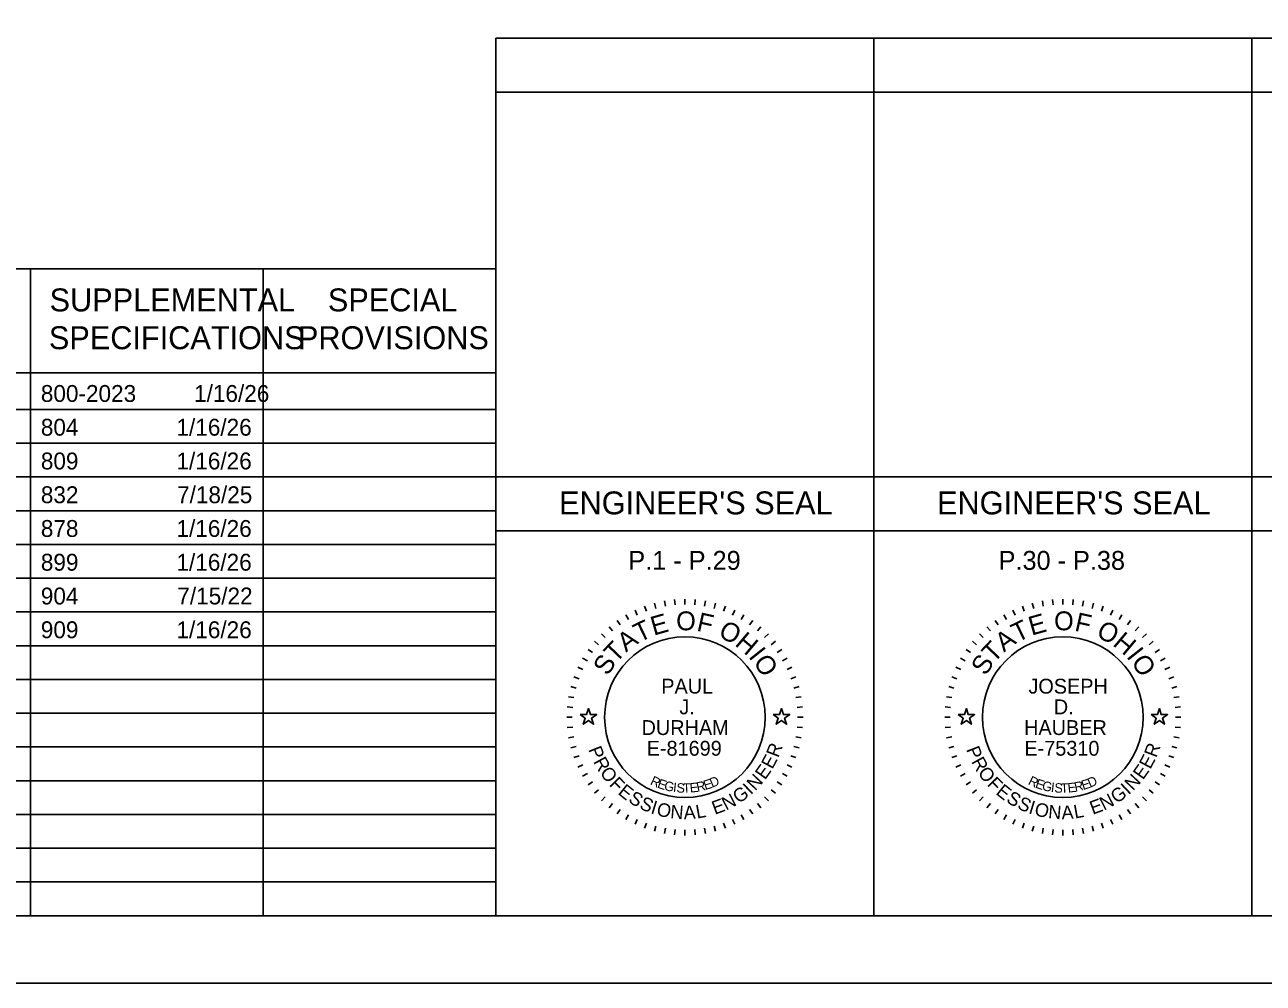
# Model space of a CAD drawing. Extents: x 0 to 34, y 0 to 22.
# Drawn here: x 20.11 to 29.28, y 0 to 7.1 of the extents above; entities that cross this region are included whole.
import ezdxf

# ---------------------------------------------------------------- set-up
doc = ezdxf.new("R2010")
doc.units = 0
for name, color, linetype in [('SH_Border', 7, 'Continuous'), ('SH_Cut_Line', 7, 'Continuous'), ('SH_Data', 7, 'Continuous'), ('SH_Seal', 7, 'Continuous'), ('SH_Text', 7, 'Continuous')]:
    doc.layers.add(name, color=color, linetype=linetype)

msp = doc.modelspace()

# ---------------------------------------------------------------- linework, layer by layer
at = {"layer": 'SH_Border'}
msp.add_lwpolyline([(1.5, 21.5), (33.5, 21.5), (33.5, 0.5), (1.5, 0.5)], close=True, dxfattribs=at)
at = {"layer": 'SH_Cut_Line'}
msp.add_lwpolyline([(0, 0), (34, 0), (34, 22), (0, 22)], close=True, dxfattribs=at)
at = {"layer": 'SH_Data'}
for p, q in [((23.6, 6.6), (26.4, 6.6)), ((26.4, 6.6), (29.2, 6.6)), ((29.2, 6.6), (32, 6.6)), ((10.15, 5.2917), (23.6, 5.2917)), ((20.15, 0.5), (20.15, 5.2917)), ((21.875, 0.5), (21.875, 5.2917)), ((23.6, 0.5), (23.6, 5.2917)), ((10.15, 4.5209), (23.6, 4.5209)), ((10.15, 4.25), (23.6, 4.25)), ((10.15, 4), (23.6, 4)), ((10.15, 3.75), (23.6, 3.75)), ((23.6, 3.75), (26.4, 3.75)), ((26.4, 0.5), (26.4, 3.75)), ((26.4, 3.75), (29.2, 3.75)), ((29.2, 0.5), (29.2, 3.75)), ((10.15, 3.5), (23.6, 3.5)), ((23.6, 3.35), (26.4, 3.35)), ((23.6, 3.35), (26.4, 3.35)), ((26.4, 3.35), (29.2, 3.35)), ((26.4, 3.35), (29.2, 3.35)), ((29.2, 3.35), (32, 3.35)), ((10.15, 3.25), (23.6, 3.25)), ((10.15, 3), (23.6, 3)), ((10.15, 2.75), (23.6, 2.75)), ((10.15, 2.5), (23.6, 2.5)), ((10.15, 2.25), (23.6, 2.25)), ((10.15, 2), (23.6, 2)), ((10.15, 1.75), (23.6, 1.75)), ((10.15, 1.5), (23.6, 1.5)), ((10.15, 1.25), (23.6, 1.25)), ((10.15, 1), (23.6, 1)), ((10.15, 0.75), (23.6, 0.75))]:
    msp.add_line(p, q, dxfattribs=at)
for points in [[(26.4, 7), (23.6, 7), (23.6, 3.75), (26.4, 3.75)], [(29.2, 7), (26.4, 7), (26.4, 3.75), (29.2, 3.75)], [(32, 7), (29.2, 7), (29.2, 3.75), (32, 3.75)], [(26.4, 3.75), (23.6, 3.75), (23.6, 0.5), (26.4, 0.5)], [(29.2, 3.75), (26.4, 3.75), (26.4, 0.5), (29.2, 0.5)], [(32, 3.75), (29.2, 3.75), (29.2, 0.5), (32, 0.5)]]:
    msp.add_lwpolyline(points, close=True, dxfattribs=at)
at = {"layer": 'SH_Seal'}
for p, q in [((25, 2.8452), (25, 2.8052)), ((27.8, 2.8452), (27.8, 2.8052)), ((24.6302, 2.7633), (24.6471, 2.727)), ((24.7007, 2.7925), (24.7144, 2.7549)), ((24.7735, 2.8154), (24.7839, 2.7768)), ((24.8481, 2.8319), (24.855, 2.7926)), ((24.9237, 2.8419), (24.9272, 2.8021)), ((25.0763, 2.8419), (25.0728, 2.8021)), ((25.1519, 2.8319), (25.145, 2.7926)), ((25.2265, 2.8154), (25.2161, 2.7768)), ((25.2993, 2.7925), (25.2856, 2.7549)), ((25.3698, 2.7633), (25.3529, 2.727)), ((27.4302, 2.7633), (27.4471, 2.727)), ((27.5007, 2.7925), (27.5144, 2.7549)), ((27.5735, 2.8154), (27.5839, 2.7768)), ((27.6481, 2.8319), (27.655, 2.7926)), ((27.7237, 2.8419), (27.7272, 2.8021)), ((27.8763, 2.8419), (27.8728, 2.8021)), ((27.9519, 2.8319), (27.945, 2.7926)), ((28.0265, 2.8154), (28.0161, 2.7768)), ((28.0993, 2.7925), (28.0856, 2.7549)), ((28.1698, 2.7633), (28.1529, 2.727)), ((24.4981, 2.687), (24.5211, 2.6542)), ((24.5625, 2.728), (24.5825, 2.6934)), ((25.4375, 2.728), (25.4175, 2.6934)), ((25.5019, 2.687), (25.4789, 2.6542)), ((27.2981, 2.687), (27.3211, 2.6542)), ((27.3625, 2.728), (27.3825, 2.6934)), ((28.2375, 2.728), (28.2175, 2.6934)), ((28.3019, 2.687), (28.2789, 2.6542)), ((24.3813, 2.589), (24.4096, 2.5607)), ((24.4376, 2.6405), (24.4633, 2.6099)), ((25.5624, 2.6405), (25.5367, 2.6099)), ((25.6187, 2.589), (25.5904, 2.5607)), ((27.1813, 2.589), (27.2096, 2.5607)), ((27.2376, 2.6405), (27.2633, 2.6099)), ((28.3624, 2.6405), (28.3367, 2.6099)), ((28.4187, 2.589), (28.3904, 2.5607)), ((24.3297, 2.5327), (24.3604, 2.507)), ((25.6703, 2.5327), (25.6396, 2.507)), ((27.1297, 2.5327), (27.1604, 2.507)), ((28.4703, 2.5327), (28.4396, 2.507)), ((24.2422, 2.4077), (24.2769, 2.3877)), ((24.2832, 2.4721), (24.316, 2.4492)), ((25.7168, 2.4721), (25.684, 2.4492)), ((25.7578, 2.4077), (25.7231, 2.3877)), ((27.0422, 2.4077), (27.0769, 2.3877)), ((27.0832, 2.4721), (27.116, 2.4492)), ((28.5168, 2.4721), (28.484, 2.4492)), ((28.5578, 2.4077), (28.5231, 2.3877)), ((24.207, 2.34), (24.2432, 2.3231)), ((25.793, 2.34), (25.7568, 2.3231)), ((27.007, 2.34), (27.0432, 2.3231)), ((28.593, 2.34), (28.5568, 2.3231)), ((24.1778, 2.2695), (24.2154, 2.2558)), ((25.8222, 2.2695), (25.7846, 2.2558)), ((26.9778, 2.2695), (27.0154, 2.2558)), ((28.6222, 2.2695), (28.5846, 2.2558)), ((24.1383, 2.1222), (24.1777, 2.1152)), ((24.1548, 2.1967), (24.1935, 2.1864)), ((25.8452, 2.1967), (25.8065, 2.1864)), ((25.8617, 2.1222), (25.8223, 2.1152)), ((26.9383, 2.1222), (26.9777, 2.1152)), ((26.9548, 2.1967), (26.9935, 2.1864)), ((28.6452, 2.1967), (28.6065, 2.1864)), ((28.6617, 2.1222), (28.6223, 2.1152)), ((24.1283, 2.0465), (24.1682, 2.043)), ((25.8717, 2.0465), (25.8318, 2.043)), ((26.9283, 2.0465), (26.9682, 2.043)), ((28.6717, 2.0465), (28.6318, 2.043)), ((24.125, 1.9702), (24.165, 1.9702)), ((25.875, 1.9702), (25.835, 1.9702)), ((26.925, 1.9702), (26.965, 1.9702)), ((28.675, 1.9702), (28.635, 1.9702)), ((24.1283, 1.894), (24.1682, 1.8975)), ((25.8717, 1.894), (25.8318, 1.8975)), ((26.9283, 1.894), (26.9682, 1.8975)), ((28.6717, 1.894), (28.6318, 1.8975)), ((24.1383, 1.8183), (24.1777, 1.8252)), ((24.1548, 1.7438), (24.1935, 1.7541)), ((25.8452, 1.7438), (25.8065, 1.7541)), ((25.8617, 1.8183), (25.8223, 1.8252)), ((26.9383, 1.8183), (26.9777, 1.8252)), ((26.9548, 1.7438), (26.9935, 1.7541)), ((28.6452, 1.7438), (28.6065, 1.7541)), ((28.6617, 1.8183), (28.6223, 1.8252)), ((24.1778, 1.671), (24.2154, 1.6847)), ((25.8222, 1.671), (25.7846, 1.6847)), ((26.9778, 1.671), (27.0154, 1.6847)), ((28.6222, 1.671), (28.5846, 1.6847)), ((24.207, 1.6005), (24.2432, 1.6174)), ((25.793, 1.6005), (25.7568, 1.6174)), ((27.007, 1.6005), (27.0432, 1.6174)), ((28.593, 1.6005), (28.5568, 1.6174)), ((24.2422, 1.5327), (24.2769, 1.5527)), ((24.2832, 1.4684), (24.316, 1.4913)), ((25.7168, 1.4684), (25.684, 1.4913)), ((25.7578, 1.5327), (25.7231, 1.5527)), ((27.0422, 1.5327), (27.0769, 1.5527)), ((27.0832, 1.4684), (27.116, 1.4913)), ((28.5168, 1.4684), (28.484, 1.4913)), ((28.5578, 1.5327), (28.5231, 1.5527)), ((24.3297, 1.4078), (24.3604, 1.4335)), ((24.3813, 1.3515), (24.4096, 1.3798)), ((25.6187, 1.3515), (25.5904, 1.3798)), ((25.6703, 1.4078), (25.6396, 1.4335)), ((27.1297, 1.4078), (27.1604, 1.4335)), ((27.1813, 1.3515), (27.2096, 1.3798)), ((28.4187, 1.3515), (28.3904, 1.3798)), ((28.4703, 1.4078), (28.4396, 1.4335)), ((24.4376, 1.3), (24.4633, 1.3306)), ((24.4981, 1.2535), (24.5211, 1.2863)), ((25.5019, 1.2535), (25.4789, 1.2863)), ((25.5624, 1.3), (25.5367, 1.3306)), ((27.2376, 1.3), (27.2633, 1.3306)), ((27.2981, 1.2535), (27.3211, 1.2863)), ((28.3019, 1.2535), (28.2789, 1.2863)), ((28.3624, 1.3), (28.3367, 1.3306)), ((24.5625, 1.2125), (24.5825, 1.2471)), ((24.6302, 1.1772), (24.6471, 1.2135)), ((25.3698, 1.1772), (25.3529, 1.2135)), ((25.4375, 1.2125), (25.4175, 1.2471)), ((27.3625, 1.2125), (27.3825, 1.2471)), ((27.4302, 1.1772), (27.4471, 1.2135)), ((28.1698, 1.1772), (28.1529, 1.2135)), ((28.2375, 1.2125), (28.2175, 1.2471)), ((24.7007, 1.148), (24.7144, 1.1856)), ((24.7735, 1.1251), (24.7839, 1.1637)), ((24.8481, 1.1085), (24.855, 1.1479)), ((24.9237, 1.0986), (24.9272, 1.1384)), ((25, 1.0952), (25, 1.1352)), ((25.0763, 1.0986), (25.0728, 1.1384)), ((25.1519, 1.1085), (25.145, 1.1479)), ((25.2265, 1.1251), (25.2161, 1.1637)), ((25.2993, 1.148), (25.2856, 1.1856)), ((27.5007, 1.148), (27.5144, 1.1856)), ((27.5735, 1.1251), (27.5839, 1.1637)), ((27.6481, 1.1085), (27.655, 1.1479)), ((27.7237, 1.0986), (27.7272, 1.1384)), ((27.8, 1.0952), (27.8, 1.1352)), ((27.8763, 1.0986), (27.8728, 1.1384)), ((27.9519, 1.1085), (27.945, 1.1479)), ((28.0265, 1.1251), (28.0161, 1.1637)), ((28.0993, 1.148), (28.0856, 1.1856))]:
    msp.add_line(p, q, dxfattribs=at)
for points in [[(24.2236, 1.9902), (24.2705, 1.9902), (24.285, 2.0348), (24.2995, 1.9902), (24.3464, 1.9902), (24.3085, 1.9626), (24.323, 1.918), (24.285, 1.9456), (24.247, 1.918), (24.2615, 1.9626)], [(25.6536, 1.9902), (25.7005, 1.9902), (25.715, 2.0348), (25.7295, 1.9902), (25.7764, 1.9902), (25.7385, 1.9626), (25.753, 1.918), (25.715, 1.9456), (25.677, 1.918), (25.6915, 1.9626)], [(27.0236, 1.9902), (27.0705, 1.9902), (27.085, 2.0348), (27.0995, 1.9902), (27.1464, 1.9902), (27.1085, 1.9626), (27.123, 1.918), (27.085, 1.9456), (27.047, 1.918), (27.0615, 1.9626)], [(28.4536, 1.9902), (28.5005, 1.9902), (28.515, 2.0348), (28.5295, 1.9902), (28.5764, 1.9902), (28.5385, 1.9626), (28.553, 1.918), (28.515, 1.9456), (28.477, 1.918), (28.4915, 1.9626)]]:
    msp.add_lwpolyline(points, close=True, dxfattribs=at)
for centre in [(25, 1.9702), (27.8, 1.9702)]:
    msp.add_circle(centre, 0.595, dxfattribs=at)

# ---------------------------------------------------------------- texts
for s, height, rotation, p in [('O', 0.14, 359.78119, (24.9347, 2.6145)), ('O', 0.14, 359.78119, (27.7347, 2.6145)), ('T', 0.14, 25.71674, (24.6616, 2.5221)), ('E', 0.14, 15.75706, (24.7684, 2.574)), ('F', 0.14, 347.43619, (25.0811, 2.612)), ('O', 0.14, 332.25863, (25.2398, 2.5718)), ('T', 0.14, 25.71674, (27.4616, 2.5221)), ('E', 0.14, 15.75706, (27.5684, 2.574)), ('F', 0.14, 347.43619, (27.8811, 2.612)), ('O', 0.14, 332.25863, (28.0398, 2.5718)), ('A', 0.14, 36.47472, (24.5634, 2.4484)), ('H', 0.14, 319.91363, (25.3632, 2.5063)), ('A', 0.14, 36.47472, (27.3634, 2.4484)), ('H', 0.14, 319.91363, (28.1632, 2.5063)), ('T', 0.14, 46.4344, (24.4883, 2.3667)), ('I', 0.14, 308.36695, (25.4665, 2.4186)), ('T', 0.14, 46.4344, (27.2883, 2.3667)), ('I', 0.14, 308.36695, (28.2665, 2.4186)), ('S', 0.14, 57.19238, (24.4281, 2.2717)), ('O', 0.14, 303.14906, (25.5021, 2.3791)), ('S', 0.14, 57.19238, (27.2281, 2.2717)), ('O', 0.14, 303.14906, (28.3021, 2.3791)), ('P', 0.1, 291.49398, (24.2823, 1.7323)), ('R', 0.1, 69.23216, (25.6919, 1.6656)), ('P', 0.1, 291.49398, (27.0823, 1.7323)), ('R', 0.1, 69.23216, (28.4919, 1.6656)), ('R', 0.1, 298.73106, (24.319, 1.6419)), ('E', 0.1, 61.99508, (25.6476, 1.5801)), ('R', 0.1, 298.73106, (27.119, 1.6419)), ('E', 0.1, 61.99508, (28.4476, 1.5801)), ('O', 0.1, 306.46664, (24.3655, 1.5585)), ('E', 0.1, 54.75801, (25.5933, 1.5016)), ('O', 0.1, 306.46664, (27.1655, 1.5585)), ('E', 0.1, 54.75801, (28.3933, 1.5016)), ('F', 0.1, 314.7068, (24.4343, 1.4685)), ('E', 0.1, 321.43929, (24.4978, 1.405)), ('R', 0.07, 334.48695, (24.7375, 1.4753)), ('E', 0.07, 341.03996, (24.7906, 1.4503)), ('G', 0.07, 347.47515, (24.8414, 1.432)), ('I', 0.07, 353.78581, (24.9091, 1.4171)), ('S', 0.07, 356.89262, (24.9358, 1.4131)), ('T', 0.07, 3.00609, (24.9857, 1.4089)), ('E', 0.07, 6.01169, (25.0389, 1.4115)), ('R', 0.07, 11.91844, (25.0925, 1.4176)), ('E', 0.07, 17.68363, (25.1498, 1.4304)), ('D', 0.07, 23.30524, (25.201, 1.4473)), ('I', 0.1, 43.28703, (25.4868, 1.3916)), ('N', 0.1, 47.02243, (25.5202, 1.421)), ('F', 0.1, 314.7068, (27.2343, 1.4685)), ('E', 0.1, 321.43929, (27.2978, 1.405)), ('R', 0.07, 334.48695, (27.5375, 1.4753)), ('E', 0.07, 341.03996, (27.5906, 1.4503)), ('G', 0.07, 347.47515, (27.6414, 1.432)), ('I', 0.07, 353.78581, (27.7091, 1.4171)), ('S', 0.07, 356.89262, (27.7358, 1.4131)), ('T', 0.07, 3.00609, (27.7857, 1.4089)), ('E', 0.07, 6.01169, (27.8389, 1.4115)), ('R', 0.07, 11.91844, (27.8925, 1.4176)), ('E', 0.07, 17.68363, (27.9498, 1.4304)), ('D', 0.07, 23.30524, (28.001, 1.4473)), ('I', 0.1, 43.28703, (28.2868, 1.3916)), ('N', 0.1, 47.02243, (28.3202, 1.421)), ('S', 0.1, 328.67637, (24.5743, 1.3455)), ('S', 0.1, 335.91345, (24.6564, 1.2968)), ('N', 0.1, 27.31129, (25.3045, 1.2777)), ('G', 0.1, 35.04687, (25.3981, 1.3272)), ('S', 0.1, 328.67637, (27.3743, 1.3455)), ('S', 0.1, 335.91345, (27.4564, 1.2968)), ('N', 0.1, 27.31129, (28.1045, 1.2777)), ('G', 0.1, 35.04687, (28.1981, 1.3272)), ('I', 0.1, 343.15053, (24.7406, 1.2599)), ('O', 0.1, 346.88592, (24.7839, 1.2454)), ('N', 0.1, 355.12608, (24.8888, 1.222)), ('A', 0.1, 2.86166, (24.9923, 1.2139)), ('L', 0.1, 10.09874, (25.0894, 1.2193)), ('E', 0.1, 20.07421, (25.2212, 1.2473)), ('I', 0.1, 343.15053, (27.5406, 1.2599)), ('O', 0.1, 346.88592, (27.5839, 1.2454)), ('N', 0.1, 355.12608, (27.6888, 1.222)), ('A', 0.1, 2.86166, (27.7923, 1.2139)), ('L', 0.1, 10.09874, (27.8894, 1.2193)), ('E', 0.1, 20.07421, (28.0212, 1.2473))]:
    msp.add_text(s, height=height, rotation=rotation, dxfattribs=at).set_placement(p)
for s, p in [('PAUL', (24.8246, 2.1452)), ('JOSEPH', (27.545, 2.1452)), ('J.', (24.9587, 1.9919)), ('D.', (27.7332, 1.9919)), ('DURHAM', (24.6785, 1.8386)), ('HAUBER', (27.5127, 1.8386)), ('E-81699', (24.7166, 1.6853)), ('E-75310', (27.5149, 1.6853))]:
    msp.add_text(s, height=0.11, dxfattribs=at).set_placement(p)
at = {"layer": 'SH_Text'}
for s, height, p in [('SUPPLEMENTAL', 0.17, (20.2925, 4.9763)), ('SPECIAL', 0.17, (22.3542, 4.9763)), ('SPECIFICATIONS', 0.17, (20.2871, 4.6963)), ('PROVISIONS', 0.17, (22.1323, 4.6963)), ('800-2023', 0.125, (20.2275, 4.3058)), ('1/16/26', 0.125, (21.3629, 4.3058)), ('804', 0.125, (20.2275, 4.0558)), ('1/16/26', 0.125, (21.2325, 4.0558)), ('809', 0.125, (20.2275, 3.8058)), ('1/16/26', 0.125, (21.2325, 3.8058)), ('832', 0.125, (20.2275, 3.5558)), ('7/18/25', 0.125, (21.2369, 3.5558)), ("ENGINEER'S SEAL", 0.17, (24.0676, 3.4727)), ("ENGINEER'S SEAL", 0.17, (26.8676, 3.4727)), ('878', 0.125, (20.2275, 3.3058)), ('1/16/26', 0.125, (21.2325, 3.3058)), ('899', 0.125, (20.2275, 3.0558)), ('1/16/26', 0.125, (21.2325, 3.0558)), ('P.1 - P.29', 0.14, (24.5807, 3.0621)), ('P.30 - P.38', 0.14, (27.3241, 3.0621)), ('7/15/22', 0.125, (21.2389, 2.8058)), ('904', 0.125, (20.2275, 2.8058)), ('909', 0.125, (20.2275, 2.5558)), ('1/16/26', 0.125, (21.2325, 2.5558))]:
    msp.add_text(s, height=height, dxfattribs=at).set_placement(p)

doc.saveas('drawing.dxf')
